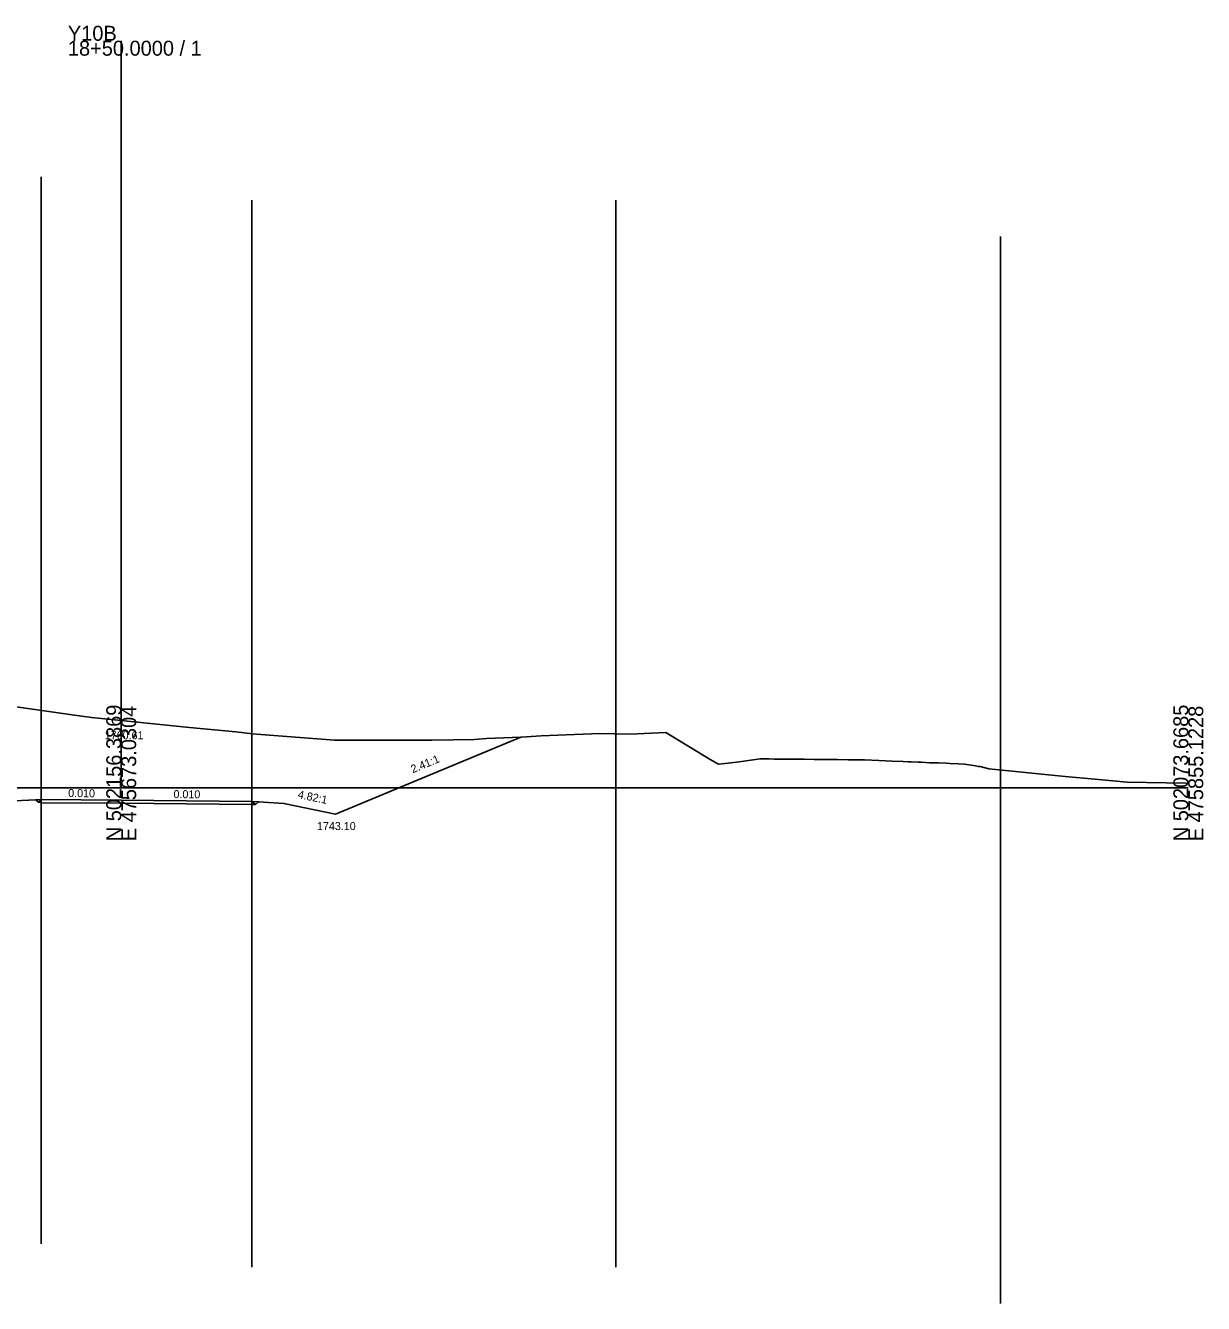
# Model space of a CAD drawing. Extents: x -26 to 1803, y -10 to 9558.
# Drawn here: x 182.1 to 402.8, y 8403.4 to 8642.9 of the extents above; entities that cross this region are included whole.
import ezdxf

# ---------------------------------------------------------------- set-up
doc = ezdxf.new("R2010")
doc.units = 0
for name, color, linetype in [('Exist Cross Section Cell', 7, 'Continuous'), ('Exist XS Center Line Elevation Label', 7, 'Continuous'), ('Exist XS Ground Line', 7, 'Continuous'), ('Prop XS Ditch Slope Text', 7, 'Continuous'), ('Prop XS Ditch Standard Text', 7, 'Continuous'), ('Prop XS Dump Level', 7, 'Continuous'), ('Prop XS Earthwork Shape', 7, 'Continuous'), ('Prop XS EOT Tick Mark', 7, 'Continuous'), ('Prop XS Finish Grade', 7, 'Continuous'), ('Prop XS Finish Grade Earthwork', 7, 'Continuous'), ('Prop XS Finish Grade Pavement', 7, 'Continuous'), ('Prop XS Hydro Typical Ditch Data', 7, 'Continuous'), ('Prop XS Pvmt Edge Slope', 7, 'Continuous'), ('Prop XS SE Text', 7, 'Continuous'), ('Prop XS Shoulder Borrow Shape', 7, 'Continuous'), ('Prop XS Side Slope Text', 7, 'Continuous'), ('Prop XS Subgrade Earthwork', 7, 'Continuous'), ('Scratch_Level_2', 7, 'Continuous')]:
    doc.layers.add(name, color=color, linetype=linetype)

msp = doc.modelspace()

# ---------------------------------------------------------------- linework, layer by layer
at = {"layer": 'Exist Cross Section Cell'}
for p, q in [((200, 8500), (200, 8640.04)), ((0, 8500), (200, 8500)), ((200, 8500), (400, 8500))]:
    msp.add_line(p, q, dxfattribs=at)
at = {"layer": 'Exist XS Ground Line'}
msp.add_lwpolyline([(179.84, 8515.27), (186.89, 8514.25), (190.83, 8513.71), (194.45, 8513.17), (200, 8512.61), (201.82, 8512.43), (202.41, 8512.38), (212.8, 8511.3), (221.45, 8510.5), (224.61, 8510.16), (226.19, 8510.03), (239.97, 8508.96), (246.18, 8508.92), (248.05, 8508.94), (258.23, 8508.97), (266.19, 8509.1), (268.44, 8509.26), (274.95, 8509.52), (278.71, 8509.74), (281.84, 8509.87), (289.7, 8510.22), (295.34, 8510.09), (302.08, 8510.37), (310.39, 8505.35), (311.93, 8504.42), (313.73, 8504.61), (315.8, 8504.9), (319.73, 8505.44), (320.38, 8505.43), (321.37, 8505.42), (322.35, 8505.41), (322.66, 8505.41), (323.94, 8505.39), (324.99, 8505.38), (325.29, 8505.37), (326.73, 8505.37), (328.04, 8505.36), (329.88, 8505.35), (330.79, 8505.34), (332.38, 8505.32), (333.53, 8505.31), (334.28, 8505.3), (336.27, 8505.29), (337.03, 8505.28), (338.8, 8505.26), (339.33, 8505.23), (342.02, 8505.11), (344.48, 8505.01), (346.54, 8504.94), (347.48, 8504.9), (348.07, 8504.88), (349.38, 8504.82), (349.97, 8504.8), (351.55, 8504.73), (352.72, 8504.69), (353.13, 8504.67), (354.62, 8504.62), (355.29, 8504.59), (356.91, 8504.52), (358.03, 8504.48), (359.28, 8504.27), (360.11, 8504.13), (360.63, 8504.04), (360.97, 8503.99), (362.64, 8503.59), (376.95, 8502.12), (382.49, 8501.63), (388.57, 8501.06), (395.87, 8500.96), (399.56, 8500.87), (400, 8500.82)], dxfattribs=at)
at = {"layer": 'Prop XS Dump Level'}
for p, q in [((185, 8497.84), (200, 8497.69)), ((200, 8497.69), (224.48, 8497.45))]:
    msp.add_line(p, q, dxfattribs=at)
at = {"layer": 'Prop XS Earthwork Shape'}
msp.add_lwpolyline([(179.84, 8515.27), (186.89, 8514.25), (190.83, 8513.71), (194.45, 8513.17), (200, 8512.61), (201.82, 8512.43), (202.41, 8512.38), (212.8, 8511.3), (221.45, 8510.5), (224.61, 8510.16), (226.19, 8510.03), (239.97, 8508.96), (246.18, 8508.92), (248.05, 8508.94), (258.23, 8508.97), (266.19, 8509.1), (268.44, 8509.26), (274.9, 8509.52), (240.15, 8495.1), (230.5, 8497.1), (225.71, 8497.38), (225.14, 8496.9), (224.48, 8496.91), (200, 8497.11), (185, 8497.23), (185, 8497.3), (184.46, 8497.31), (183.98, 8497.79), (180, 8497.59)], dxfattribs=at)
at = {"layer": 'Prop XS EOT Tick Mark'}
for p, q in [((185, 8497.84), (185, 8498.84)), ((224.48, 8497.45), (224.48, 8498.45))]:
    msp.add_line(p, q, dxfattribs=at)
at = {"layer": 'Prop XS Finish Grade'}
for p, q in [((185, 8497.84), (183.98, 8497.79)), ((224.48, 8497.45), (225.71, 8497.38))]:
    msp.add_line(p, q, dxfattribs=at)
at = {"layer": 'Prop XS Finish Grade Earthwork'}
for p, q in [((240.15, 8495.1), (274.9, 8509.52)), ((183.98, 8497.79), (180, 8497.59)), ((225.71, 8497.38), (230.5, 8497.1)), ((230.5, 8497.1), (240.15, 8495.1))]:
    msp.add_line(p, q, dxfattribs=at)
at = {"layer": 'Prop XS Finish Grade Pavement'}
for p, q in [((185, 8497.84), (200, 8497.69)), ((200, 8497.69), (224.48, 8497.45))]:
    msp.add_line(p, q, dxfattribs=at)
at = {"layer": 'Prop XS Hydro Typical Ditch Data'}
for p, q in [((240.15, 8495.1), (274.9, 8509.52)), ((230.5, 8497.1), (240.15, 8495.1))]:
    msp.add_line(p, q, dxfattribs=at)
at = {"layer": 'Prop XS Pvmt Edge Slope'}
for p, q in [((185, 8497.84), (184.46, 8497.31)), ((224.48, 8497.45), (225.14, 8496.9))]:
    msp.add_line(p, q, dxfattribs=at)
at = {"layer": 'Prop XS Shoulder Borrow Shape'}
for points in [[(185, 8497.84), (183.98, 8497.79), (184.46, 8497.31)], [(224.48, 8497.45), (225.14, 8496.9), (225.71, 8497.38)]]:
    msp.add_lwpolyline(points, close=True, dxfattribs=at)
at = {"layer": 'Prop XS Subgrade Earthwork'}
for p, q in [((184.46, 8497.31), (183.98, 8497.79)), ((185, 8497.3), (184.46, 8497.31)), ((185, 8497.23), (185, 8497.3)), ((200, 8497.11), (185, 8497.23)), ((224.48, 8496.91), (200, 8497.11)), ((224.48, 8496.91), (225.14, 8496.9)), ((225.14, 8496.9), (225.71, 8497.38))]:
    msp.add_line(p, q, dxfattribs=at)
at = {"layer": 'Scratch_Level_2'}
for p, q in [((185, 8614.52), (185, 8414.52)), ((224.48, 8610.17), (224.48, 8410.17)), ((292.71, 8610.15), (292.71, 8410.15)), ((364.79, 8603.37), (364.79, 8403.37))]:
    msp.add_line(p, q, dxfattribs=at)

# ---------------------------------------------------------------- texts
at = {"layer": 'Exist Cross Section Cell'}
for s, p in [('Y10B', (190, 8640.04)), ('18+50.0000 / 1', (190, 8637.24))]:
    msp.add_text(s, height=2.8, dxfattribs=at).set_placement(p)
for s, p in [('N 502156.3869', (200, 8490)), ('E 475673.0304', (202.8, 8490)), ('N 502073.6685', (400, 8490)), ('E 475855.1228', (402.8, 8490))]:
    msp.add_text(s, height=2.8, rotation=90, dxfattribs=at).set_placement(p)
at = {"layer": 'Exist XS Center Line Elevation Label'}
msp.add_text('1760.61', height=1.5, dxfattribs=at).set_placement((196.91, 8509.11))
at = {"layer": 'Prop XS Ditch Slope Text'}
msp.add_text('4.82:1', height=1.5, rotation=348.2823, dxfattribs=at).set_placement((233.01, 8498.11))
at = {"layer": 'Prop XS Ditch Standard Text'}
msp.add_text('1743.10', height=1.5, dxfattribs=at).set_placement((236.69, 8492.1))
at = {"layer": 'Prop XS Dump Level'}
msp.add_text('Case1', height=0.04, dxfattribs=at).set_placement((230.5, 8497.06))
at = {"layer": 'Prop XS SE Text'}
for p in [(190.05, 8498.29), (209.79, 8498.09)]:
    msp.add_text('0.010', height=1.5, rotation=359.4271, dxfattribs=at).set_placement(p)
at = {"layer": 'Prop XS Side Slope Text'}
msp.add_text('2.41:1', height=1.5, rotation=22.5298, dxfattribs=at).set_placement((254.65, 8502.74))

doc.saveas('drawing.dxf')
